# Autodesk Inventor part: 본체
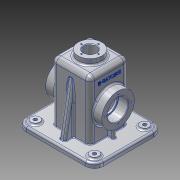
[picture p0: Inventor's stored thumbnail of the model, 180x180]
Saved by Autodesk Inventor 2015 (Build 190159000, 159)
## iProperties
Created: 2016-02
Part Number: 본체
Material: 알루미늄 6061
Document SubType Name: Modeling
Designer: Administrator
Density: 2.7 g/cm^3
Appearance: 알루미늄 - 평지
Mass: 783.394 g
Surface Area: 909.509 cm^2
Volume: 290.146 cm^3
Author: Administrator
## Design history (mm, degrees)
sketch "스케치1"
  geometry: L1 (-65, -57.5)-(65, -57.5); L2 (65, -57.5)-(65, 57.5); L3 (65, 57.5)-(-65, 57.5); L4 (-65, 57.5)-(-65, -57.5); 3 further points
  constraints: 8 end point, 2 midpoint, 2 parallel, 1 horizontal, 1 horizontal alignment, 1 perpendicular, 1 vertical alignment
  dimensions: "d0" = 130 distance of L2.end L3.end; "d1" = 115 distance of L1.end L2.end
extrude "돌출1" new body sketch "스케치1" distance "d2" = 8; taper "d3" = 0 deg
sketch "스케치2"
  geometry: L1 (-60, -52.5)-(60, -52.5); L2 (60, -52.5)-(60, 52.5); L3 (60, 52.5)-(-60, 52.5); L4 (-60, 52.5)-(-60, -52.5); 3 further points
  constraints: 8 end point, 2 midpoint, 2 parallel, 1 horizontal, 1 horizontal alignment, 1 perpendicular, 1 vertical alignment
  dimensions: "d4" = 105 distance of L3.end L1.start; "d5" = 120 distance of L2.end L3.end
extrude "돌출2" join sketch "스케치2" distance "d6" = 2; taper "d7" = 0 deg
sketch "스케치3"
  geometry: L1 (-32.5, -32.5)-(32.5, -32.5); L2 (32.5, -32.5)-(32.5, 32.5); L3 (32.5, 32.5)-(-32.5, 32.5); L4 (-32.5, 32.5)-(-32.5, -32.5); 3 further points
  constraints: 8 end point, 2 midpoint, 2 parallel, 1 horizontal, 1 horizontal alignment, 1 perpendicular, 1 vertical alignment
  dimensions: "d8" = 65 distance of L2.end L3.end; "d9" = 65 distance of L1.end L2.end
extrude "돌출3" join sketch "스케치3" distance "d10" = 100; taper "d11" = 0 deg
sketch "스케치4"
  geometry: L1 (27.5, -27.5)-(-27.5, -27.5); L2 (-27.5, -27.5)-(-27.5, 27.5); L3 (-27.5, 27.5)-(27.5, 27.5); L4 (27.5, 27.5)-(27.5, -27.5); 3 further points
  constraints: 8 end point, 2 midpoint, 2 parallel, 1 horizontal, 1 horizontal alignment, 1 perpendicular, 1 vertical alignment
  dimensions: "d12" = 55 distance of L1.end L2.end; "d13" = 55 distance of L2.end L3.end
extrude "돌출4" cut sketch "스케치4" distance "d14" = 105; taper "d15" = 0 deg
sketch "스케치5"
  geometry: C1 r 20 at (0, 0); 1 further point
  constraints: 1 centre point, 1 coincident
  dimensions: "d16" = 40 diameter of C1
extrude "돌출5" join sketch "스케치5" distance "d17" = 10; taper "d18" = 0 deg
hole "구멍1" diameter "d21" = 21; stored, may be unused: countersink angle "d25" = 90 deg, drill point angle "d27" = 118 deg; dims "d19" = 10, "d20" = 10, "d22" = 6, "d23" = 4, "d24" = 2, "d26" = 8
sketch "스케치7"
  geometry: C1 r 10.5 at (0, 0) reference; C2 r 20 at (0, 0) reference; 5 further points
  constraints: 2 horizontal alignment, 2 vertical alignment
  dimensions: "d28" = 14.5 distance of point (-14.5, 0) point (0, 0); "d29" = 14.5 distance of point (0, 0) point (0, 14.5); "d30" = 14.5 distance of point (0, 0) point (14.5, 0); "d31" = 14.5 distance of point (0, 0) point (0, -14.5)
hole "구멍2" sketch "스케치7" at (-14.5, 0), (0, 14.5), (14.5, 0), (0, -14.5) diameter "d32" = 2.459; stored, may be unused: countersink angle "d36" = 90 deg, drill point angle "d38" = 118 deg; dims "d33" = 7, "d34" = 4, "d35" = 2, "d37" = 9
fillet "모깎기1" dims "d43" = 15
sketch "스케치9"
  geometry: L1 (-50, 57.5)-(50, 57.5) reference; L2 (65, 42.5)-(65, -42.5) reference; L3 (50, -57.5)-(-50, -57.5) reference; L4 (-65, -42.5)-(-65, 42.5) reference; L5 (-27.5, 27.5)-(-27.5, -27.5) reference; L6 (-27.5, -27.5)-(27.5, -27.5) reference; L7 (27.5, -27.5)-(27.5, 27.5) reference; L8 (27.5, 27.5)-(-27.5, 27.5) reference; L9 (-32.5, -32.5)-(-32.5, 32.5) reference; L10 (-32.5, 32.5)-(32.5, 32.5) reference; L11 (32.5, 32.5)-(32.5, -32.5) reference; L12 (32.5, -32.5)-(-32.5, -32.5) reference; C1 r 7.5 at (-50, 42.5); C2 r 7.5 at (50, 42.5); C3 r 7.5 at (50, -42.5); C4 r 7.5 at (-50, -42.5); A1 r 15 centre (-50, 42.5) between (-50, 57.5) and (-65, 42.5) reference; A2 r 15 centre (50, 42.5) between (65, 42.5) and (50, 57.5) reference; A3 r 15 centre (50, -42.5) between (50, -57.5) and (65, -42.5) reference; A4 r 15 centre (-50, -42.5) between (-65, -42.5) and (-50, -57.5) reference; 1 further point
  constraints: 4 centre point, 4 coincident
  dimensions: "d44" = 15 diameter of C1; "d45" = 15 diameter of C2; "d46" = 15 diameter of C3; "d47" = 15 diameter of C4
extrude "돌출6" join sketch "스케치9" distance "d48" = 3; taper "d49" = 0 deg
hole "구멍3" diameter "d52" = 6; stored, may be unused: countersink angle "d56" = 90 deg, drill point angle "d58" = 118 deg; dims "d50" = 10, "d51" = 10, "d53" = 7, "d54" = 4, "d55" = 2, "d57" = 9
sketch "스케치10"
  geometry: L1 (10, -20)-(8, -20) reference; L2 (8, -20)-(8, -25) reference; L3 (8, -25)-(0, -25) reference; L4 (0, -25)-(0, 0) reference; L5 (0, 0)-(0, 65) reference; L6 (0, 65)-(0, 90) reference; L7 (0, 90)-(8, 90) reference; L8 (8, 90)-(8, 85) reference; L9 (8, 85)-(10, 85) reference; L10 (10, 85)-(10, -20) reference; L11 (0, 0)-(-100, 0) reference; L12 (-100, 0)-(-100, 65) reference; L13 (-100, 65)-(0, 65) reference; C1 r 27.5 at (-45, 32.5); 2 further points
  constraints: 1 centre point, 1 horizontal alignment, 1 midpoint
  dimensions: "d59" = 55 diameter of C1; "d60" = 55 distance from line of L10 C1.centre
extrude "돌출7" join sketch "스케치10" distance "d61" = 15; taper "d62" = 0 deg
sketch "스케치11"
  geometry: L1 (45, 35.429)-(42, 35.429) reference; L2 (42, 35.429)-(42, 40.842) reference; L3 (42, 40.842)-(55, 40.842) reference; L4 (55, 40.842)-(55, -40.842) reference; L5 (55, -40.842)-(42, -40.842) reference; L6 (42, -40.842)-(42, -35.429) reference; L7 (42, -35.429)-(45, -35.429) reference; L8 (45, -35.429)-(45, 35.429) reference; L9 (53, 52.5)-(55, 52.5) reference; L10 (55, 52.5)-(55, 44.158) reference; L11 (55, 44.158)-(42, 44.158) reference; L12 (42, 44.158)-(42, 49.571) reference; L13 (42, 49.571)-(45, 49.571) reference; L14 (45, 49.571)-(45, 57.5) reference; L15 (45, 57.5)-(53, 57.5) reference; L16 (53, 57.5)-(53, 52.5) reference; L17 (55, -52.5)-(53, -52.5) reference; L18 (53, -52.5)-(53, -57.5) reference; L19 (53, -57.5)-(45, -57.5) reference; L20 (45, -57.5)-(45, -49.571) reference; L21 (45, -49.571)-(42, -49.571) reference; L22 (42, -49.571)-(42, -44.158) reference; L23 (42, -44.158)-(55, -44.158) reference; L24 (55, -44.158)-(55, -52.5) reference; C1 r 27.5 at (0, 0) reference; C2 r 17.5 at (0, 0); 1 further point
  constraints: 1 centre point, 1 coincident
  dimensions: "d63" = 35 diameter of C2
extrude "돌출8" cut sketch "스케치11" distance "d64" = 17; taper "d65" = 0 deg
sketch "스케치12"
  geometry: L1 (55, -52.5)-(53, -52.5) reference; L2 (53, -52.5)-(53, -57.5) reference; L3 (53, -57.5)-(45, -57.5) reference; L4 (45, -57.5)-(45, -32.5) reference; L5 (45, -32.5)-(-55, -32.5) reference; L6 (-55, -32.5)-(-55, 32.5) reference; L7 (-55, 32.5)-(45, 32.5) reference; L8 (45, 32.5)-(45, 57.5) reference; L9 (45, 57.5)-(53, 57.5) reference; L10 (53, 57.5)-(53, 52.5) reference; L11 (53, 52.5)-(55, 52.5) reference; L12 (55, 52.5)-(55, -52.5) reference; C1 r 17.5 at (0, 0) reference; C2 r 15 at (0, 0); 1 further point
  constraints: 1 centre point, 1 coincident
  dimensions: "d66" = 30 diameter of C2
extrude "돌출9" cut sketch "스케치12" distance "d67" = 4; taper "d68" = 0 deg
sketch "스케치13"
  geometry: L1 (45, 35.429)-(42, 35.429) reference; L2 (42, 35.429)-(42, 40.842) reference; L3 (42, 40.842)-(55, 40.842) reference; L4 (55, 40.842)-(55, -40.842) reference; L5 (55, -40.842)-(42, -40.842) reference; L6 (42, -40.842)-(42, -35.429) reference; L7 (42, -35.429)-(45, -35.429) reference; L8 (45, -35.429)-(45, 35.429) reference; L9 (53, 52.5)-(55, 52.5) reference; L10 (55, 52.5)-(55, 44.158) reference; L11 (55, 44.158)-(42, 44.158) reference; L12 (42, 44.158)-(42, 49.571) reference; L13 (42, 49.571)-(45, 49.571) reference; L14 (45, 49.571)-(45, 57.5) reference; L15 (45, 57.5)-(53, 57.5) reference; L16 (53, 57.5)-(53, 52.5) reference; L17 (55, -52.5)-(53, -52.5) reference; L18 (53, -52.5)-(53, -57.5) reference; L19 (53, -57.5)-(45, -57.5) reference; L20 (45, -57.5)-(45, -49.571) reference; L21 (45, -49.571)-(42, -49.571) reference; L22 (42, -49.571)-(42, -44.158) reference; L23 (42, -44.158)-(55, -44.158) reference; L24 (55, -44.158)-(55, -52.5) reference; C1 r 17.5 at (0, 0) reference; C2 r 27.5 at (0, 0) reference; 5 further points
  constraints: 2 horizontal alignment, 2 vertical alignment
  dimensions: "d69" = 21 distance of C1.centre point (-21, 0); "d70" = 21 distance of C1.centre point (0, 21); "d71" = 21 distance of C1.centre point (21, 0); "d72" = 21 distance of point (0, -21) C1.centre
hole "구멍4" sketch "스케치13" at (-21, 0), (0, 21), (21, 0), (0, -21) diameter "d73" = 3.242; stored, may be unused: countersink angle "d77" = 90 deg, drill point angle "d79" = 118 deg; dims "d74" = 8, "d75" = 4, "d76" = 2, "d78" = 10
chamfer "모따기1" distance "d80" = 1; stored, may be unused: second distance "d81" = 2, angle "d82" = 45 deg
chamfer "모따기2" distance "d83" = 1; stored, may be unused: second distance "d84" = 2, angle "d85" = 45 deg
sketch "스케치14"
  geometry: L1 (-42.161, 38.278)-(-47.5, 8); L2 (-57.5, 8)-(-57.5, 0) reference; L3 (-42.5, 8)-(42.5, 8) reference; L4 (-32.5, 8)-(-32.5, 108) reference; 1 further point
  constraints: 2 end point, 1 horizontal alignment
  dimensions: "d88" = 10 distance from line of L2 L1.end; "d123" = 10 deg angle of L2 L1; "d124" = 9.66119 distance from line of L4 L1.start
feature "리브1" sketch "스케치14" dims "d90" = 1, "d91" = 10, "d92" = 0, "d93" = 0, "d94" = 1, "d95" = 1
fillet "모깎기2" dims "d96" = 3
fillet "모깎기3" dims "d97" = 3
fillet "모깎기4" dims "d98" = 3
fillet "모깎기5" dims "d99" = 3
sketch "스케치15"
  geometry: L1 (5, -35.5)-(5, -44.454) reference; L2 (2, -47.5)-(-2, -47.5) reference; L3 (-5, -44.454)-(-5, -35.5) reference; L4 (-8, -32.5)-(-32.5, -32.5) reference; L5 (-32.5, -32.5)-(-32.5, 32.5) reference; L6 (-32.5, 32.5)-(-8, 32.5) reference; L7 (-5, 35.5)-(-5, 44.454) reference; L8 (-2, 47.5)-(2, 47.5) reference; L9 (5, 44.454)-(5, 35.5) reference; L10 (8, 32.5)-(32.5, 32.5) reference; L11 (32.5, 32.5)-(32.5, -32.5) reference; L12 (32.5, -32.5)-(8, -32.5) reference; L13 (27.5, 27.5)-(-27.5, 27.5) reference; L14 (-27.5, 27.5)-(-27.5, -27.5) reference; L15 (-27.5, -27.5)-(27.5, -27.5) reference; L16 (27.5, -27.5)-(27.5, 27.5) reference; L17 (-50, 57.5)-(50, 57.5) reference; L18 (65, 42.5)-(65, -42.5) reference; L19 (50, -57.5)-(-50, -57.5) reference; L20 (-65, -42.5)-(-65, 42.5) reference; L21 (32.5, -3)-(42.5, -3); L22 (42.5, -3)-(42.5, 3); L23 (42.5, 3)-(32.5, 3); L24 (32.5, 3)-(32.5, -3); C1 r 3 at (50, 42.5) reference; C2 r 3 at (50, -42.5) reference; C3 r 3 at (-50, 42.5) reference; C4 r 3 at (-50, -42.5) reference; C5 r 7.5 at (50, -42.5) reference; C6 r 7.5 at (-50, 42.5) reference; C7 r 7.5 at (50, 42.5) reference; C8 r 7.5 at (-50, -42.5) reference; A1 r 3 centre (8, -35.5) between (8, -32.5) and (5, -35.5) reference; A2 r 3 centre (-8, -35.5) between (-5, -35.5) and (-8, -32.5) reference; A3 r 3 centre (-8, 35.5) between (-8, 32.5) and (-5, 35.5) reference; A4 r 3 centre (8, 35.5) between (5, 35.5) and (8, 32.5) reference; A5 r 15 centre (-50, 42.5) between (-50, 57.5) and (-65, 42.5) reference; A6 r 15 centre (50, 42.5) between (65, 42.5) and (50, 57.5) reference; A7 r 15 centre (50, -42.5) between (50, -57.5) and (65, -42.5) reference; A8 r 15 centre (-50, -42.5) between (-65, -42.5) and (-50, -57.5) reference; 6 further points; 4 other entities
  constraints: 8 end point, 2 parallel, 1 horizontal, 1 horizontal alignment, 1 midpoint, 1 perpendicular, 1 point on line, 4 other
  dimensions: "d101" = 6 distance of L21.end L22.end; "d104" = 15 distance between parallel lines of L16 L22
extrude "돌출10" join sketch "스케치15" stored distance "d102" = 4; taper "d103" = 0 deg
fillet "모깎기8" dims "d107" = 0.3
fillet "모깎기10" dims "d109" = 8
fillet "모깎기12" dims "d111" = 3
fillet "모깎기13" dims "d112" = 3
fillet "모깎기14" dims "d113" = 1
node "작업 평면1"
sketch "스케치16"
  geometry: L1 (-32.5, 108)-(-32.5, 9) reference; L2 (20, 118)-(-20, 118) reference; 3 further points
  constraints: 1 other
  dimensions: "d115" = 32.5 distance from line of point (0, 92) L1; "d116" = 26 distance from line of point (0, 92) L2
feature "엠보싱1" sketch "스케치16" dims "d8" = 65, "d9" = 65, "d117" = 0.5, "d118" = 0
fillet "모깎기15" dims "d119" = 10
fillet "모깎기17" dims "d125" = 8
fillet "모깎기18" dims "d126" = 3
fillet "모깎기19" dims "d127" = 3
node "솔리드1"
mirror "대칭1"
mirror "대칭2"
mirror "대칭3"
mirror "대칭4"
mirror "대칭5"
node "절단 모서리 투영1"
node "절단 모서리 투영3"
node "절단 모서리 투영4"
node "절단 모서리 투영5"
node "절단 모서리 투영6"
node "절단 모서리 투영7"
node "절단 모서리 투영8"
other parameters: "d114" = 98.5
